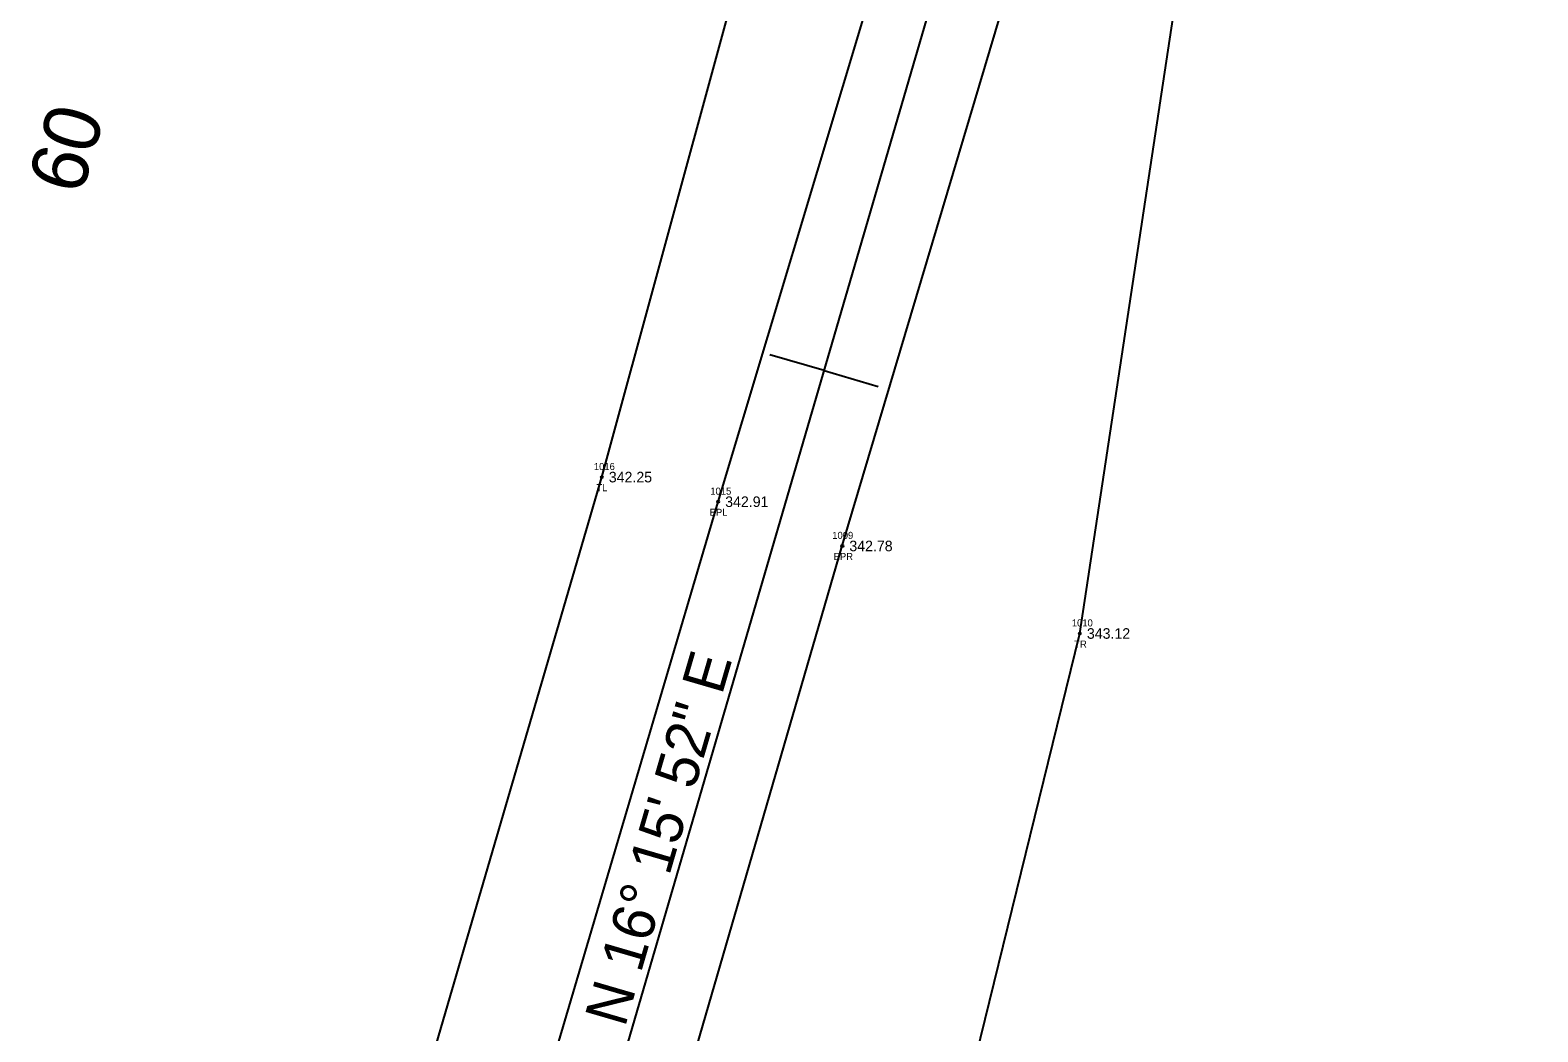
# Model space of a CAD drawing. Extents: x 2231119 to 2232595, y 1035731 to 1037094.
# Drawn here: x 2231119.1 to 2231332.8, y 1035871.8 to 1036013.8 of the extents above; entities that cross this region are included whole.
import ezdxf

# ---------------------------------------------------------------- set-up
doc = ezdxf.new("R2010")
doc.units = 0
for name, color, linetype in [('RD_EX_Road', 7, 'Continuous'), ('RD_EX_Road_txCode', 7, 'Continuous'), ('RD_EX_TX_Road_ELEV', 7, 'Continuous'), ('RD_EX_TX_VEG_ELEV', 7, 'Continuous'), ('RD_EX_VEG', 7, 'Continuous'), ('RD_EX_VEG_txCode', 7, 'Continuous'), ('RD_HC_Cl', 7, 'Continuous'), ('RD_HC_Data', 7, 'Continuous'), ('RD_HC_Data_Tic', 7, 'Continuous'), ('RD_HC_TX_Sta50', 7, 'Continuous'), ('RD_SMD_Locator', 7, 'Continuous')]:
    doc.layers.add(name, color=color, linetype=linetype)

msp = doc.modelspace()

# ---------------------------------------------------------------- linework, layer by layer
at = {"layer": 'RD_EX_Road'}
for points in [[(2231158.42, 1035748.11), (2231188.37, 1035851.38), (2231216.59, 1035946.92), (2231244.77, 1036040.72), (2231278.59, 1036133.31), (2231299.55, 1036179.73), (2231323.11, 1036221.2), (2231350.7, 1036262.3), (2231381.59, 1036299.29), (2231415.97, 1036336.9), (2231452.94, 1036369.74), (2231498.19, 1036405.3), (2231537.2, 1036432.57), (2231541.46, 1036424.96)], [(2231176.43, 1035742.89), (2231206.61, 1035845.83), (2231234.19, 1035940.65), (2231261.92, 1036033.75), (2231294.68, 1036125.28), (2231316.11, 1036171.75), (2231338.19, 1036211.09), (2231363.83, 1036252.38), (2231394.08, 1036289.28), (2231427.67, 1036324.2), (2231464.37, 1036355.5), (2231508.96, 1036392.41), (2231546.55, 1036416.22), (2231541.46, 1036424.96)]]:
    msp.add_lwpolyline(points, dxfattribs=at)
at = {"layer": 'RD_EX_VEG'}
for points in [[(2231141.61, 1035753.39), (2231172.54, 1035856.04), (2231200.09, 1035950.41), (2231226.19, 1036046.04), (2231262.9, 1036139.62), (2231281.03, 1036187.82), (2231303.66, 1036232.51), (2231318.61, 1036284.65), (2231353.84, 1036322.59), (2231394.02, 1036358.2), (2231443.85, 1036383.78)], [(2231211.01, 1035732.98), (2231244.87, 1035834.47), (2231267.87, 1035928.24), (2231283.13, 1036029.08), (2231316.25, 1036116.26), (2231338.15, 1036162.94), (2231357.98, 1036198.54), (2231413.07, 1036272.2), (2231445.22, 1036302.16), (2231483.09, 1036338.47), (2231530.02, 1036372.29)]]:
    msp.add_lwpolyline(points, dxfattribs=at)
at = {"layer": 'RD_HC_Cl'}
msp.add_line((2231167.43, 1035745.5), (2231256.91, 1036052.22), dxfattribs=at)
at = {"layer": 'RD_HC_Data_Tic'}
for q in [(2231223.93, 1035967.74), (2231239.29, 1035963.26)]:
    msp.add_line((2231231.61, 1035965.5), q, dxfattribs=at)
at = {"layer": 'RD_SMD_Locator'}
for centre in [(2231200.09, 1035950.41), (2231216.59, 1035946.92), (2231234.19, 1035940.65), (2231267.87, 1035928.24)]:
    msp.add_circle(centre, 0.15, dxfattribs=at)

# ---------------------------------------------------------------- texts
at = {"layer": 'RD_EX_Road_txCode'}
for s, p in [('1015', (2231215.48, 1035947.92)), ('EPL', (2231215.38, 1035944.92)), ('1009', (2231232.77, 1035941.65)), ('EPR', (2231232.96, 1035938.65))]:
    msp.add_text(s, height=1, dxfattribs=at).set_placement(p)
at = {"layer": 'RD_EX_TX_Road_ELEV'}
for s, p in [('342.91', (2231217.59, 1035946.17)), ('342.78', (2231235.19, 1035939.9))]:
    msp.add_text(s, height=1.5, dxfattribs=at).set_placement(p)
at = {"layer": 'RD_EX_TX_VEG_ELEV'}
for s, p in [('342.25', (2231201.09, 1035949.66)), ('343.12', (2231268.87, 1035927.49))]:
    msp.add_text(s, height=1.5, dxfattribs=at).set_placement(p)
at = {"layer": 'RD_EX_VEG_txCode'}
for s, p in [('1016', (2231198.97, 1035951.41)), ('TL', (2231199.32, 1035948.41)), ('1010', (2231266.73, 1035929.24)), ('TR', (2231267.07, 1035926.24))]:
    msp.add_text(s, height=1, dxfattribs=at).set_placement(p)
at = {"layer": 'RD_HC_Data'}
msp.add_text('N 16%%d 15\' 52" E', height=6, rotation=73.7355, dxfattribs=at).set_placement((2231203.37, 1035872.28))
at = {"layer": 'RD_HC_TX_Sta50'}
msp.add_text('60', height=8, rotation=73.7355, dxfattribs=at).set_placement((2231126.31, 1035990.18))

doc.saveas('drawing.dxf')
